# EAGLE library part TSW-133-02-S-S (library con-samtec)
THROUGH-HOLE .025" SQ POST HEADER Source: Samtec TSW.pdf
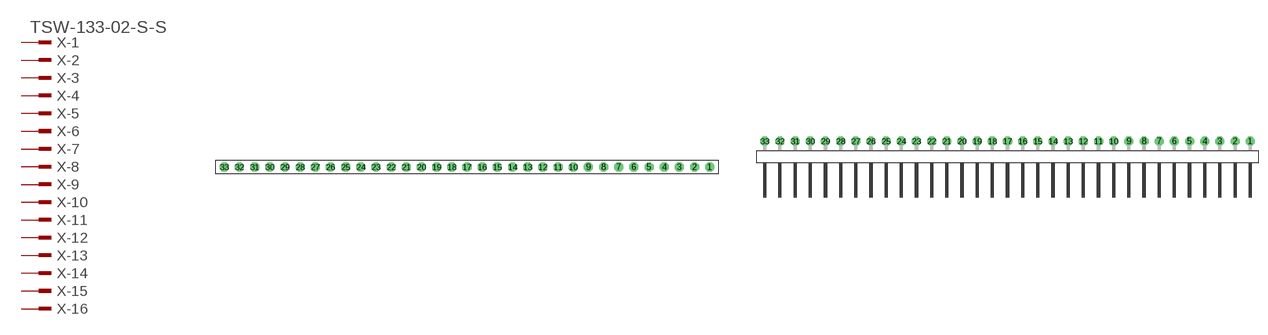
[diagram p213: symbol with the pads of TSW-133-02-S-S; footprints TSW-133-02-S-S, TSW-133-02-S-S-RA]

Designator prefix X; gates -1=MPINV -2=MPIN -3=MPIN -4=MPIN -5=MPIN -6=MPIN -7=MPIN -8=MPIN -9=MPIN -10=MPIN -11=MPIN -12=MPIN -13=MPIN -14=MPIN -15=MPIN -16=MPIN -17=MPIN -18=MPIN -19=MPIN -20=MPIN -21=MPIN -22=MPIN -23=MPIN -24=MPIN -25=MPIN -26=MPIN -27=MPIN -28=MPIN -29=MPIN -30=MPIN -31=MPIN -32=MPIN -33=MPIN

## TSW-133-02-S-S (OC_FARNELL: unknown; OC_NEWARK: unknown)  [TSW-133-02-S-S]
1  -1:1  pas
2  -2:1  pas
3  -3:1  pas
4  -4:1  pas
5  -5:1  pas
6  -6:1  pas
7  -7:1  pas
8  -8:1  pas
9  -9:1  pas
10  -10:1  pas
11  -11:1  pas
12  -12:1  pas
13  -13:1  pas
14  -14:1  pas
15  -15:1  pas
16  -16:1  pas
17  -17:1  pas
18  -18:1  pas
19  -19:1  pas
20  -20:1  pas
21  -21:1  pas
22  -22:1  pas
23  -23:1  pas
24  -24:1  pas
25  -25:1  pas
26  -26:1  pas
27  -27:1  pas
28  -28:1  pas
29  -29:1  pas
30  -30:1  pas
31  -31:1  pas
32  -32:1  pas
33  -33:1  pas

## TSW-133-02-S-S-RA (OC_FARNELL: unknown; OC_NEWARK: unknown)  [TSW-133-02-S-S-RA]
Pads as for TSW-133-02-S-S

## Footprint TSW-133-02-S-S (pad centres in mm)
THROUGH-HOLE .025" SQ POST HEADER Source: Samtec TSW.pdf
drill 1 pad 1.5 octagon: 1 40.64,0; 2 38.1,0; 3 35.56,0; 4 33.02,0; 5 30.48,0; 6 27.94,0; 7 25.4,0; 8 22.86,0; 9 20.32,0; 10 17.78,0; 11 15.24,0; 12 12.7,0; 13 10.16,0; 14 7.62,0; 15 5.08,0; 16 2.54,0; 17 0,0; 18 -2.54,0; 19 -5.08,0; 20 -7.62,0; 21 -10.16,0; 22 -12.7,0; 23 -15.24,0; 24 -17.78,0; 25 -20.32,0; 26 -22.86,0; 27 -25.4,0; 28 -27.94,0; 29 -30.48,0; 30 -33.02,0; 31 -35.56,0; 32 -38.1,0; 33 -40.64,0

## Footprint TSW-133-02-S-S-RA (pad centres in mm)
THROUGH-HOLE .025" SQ POST HEADER Source: Samtec TSW.pdf
drill 1 pad 1.5 octagon: 1 40.64,1.524; 2 38.1,1.524; 3 35.56,1.524; 4 33.02,1.524; 5 30.48,1.524; 6 27.94,1.524; 7 25.4,1.524; 8 22.86,1.524; 9 20.32,1.524; 10 17.78,1.524; 11 15.24,1.524; 12 12.7,1.524; 13 10.16,1.524; 14 7.62,1.524; 15 5.08,1.524; 16 2.54,1.524; 17 0,1.524; 18 -2.54,1.524; 19 -5.08,1.524; 20 -7.62,1.524; 21 -10.16,1.524; 22 -12.7,1.524; 23 -15.24,1.524; 24 -17.78,1.524; 25 -20.32,1.524; 26 -22.86,1.524; 27 -25.4,1.524; 28 -27.94,1.524; 29 -30.48,1.524; 30 -33.02,1.524; 31 -35.56,1.524; 32 -38.1,1.524; 33 -40.64,1.524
